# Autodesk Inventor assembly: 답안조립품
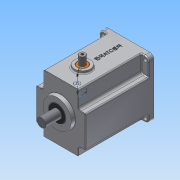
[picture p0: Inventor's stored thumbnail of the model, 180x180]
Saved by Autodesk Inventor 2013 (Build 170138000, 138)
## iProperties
Created: 2016-02
Part Number: 답안조립품
Document SubType Name: Assembly
Designer: Administrator
Author: Administrator
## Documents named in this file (13)
- C:\Users\Administrator\Desktop\360212V1023\답안조립품.iam
- C:\Users\Administrator\Desktop\360212V1023\본체.ipt
- C:\Users\Administrator\Desktop\360212V1023\커버.ipt
- C:\Users\Administrator\Desktop\360212V1023\오일실 17 32 8.ipt
- C:\Users\Administrator\Desktop\360212V1023\오일실 8 22 7.ipt
- C:\Users\Administrator\Desktop\360212V1023\부시.ipt
- C:\Users\Administrator\Desktop\360212V1023\베어링 608.ipt
- C:\Users\Administrator\Desktop\360212V1023\베어링 6003.ipt
- C:\Users\Administrator\Desktop\360212V1023\볼트 M4 x 10.ipt
- C:\Users\Administrator\Desktop\360212V1023\슬라이더.ipt
- C:\Users\Administrator\Desktop\360212V1023\메인축.ipt
- C:\Users\Administrator\Desktop\360212V1023\서브축.ipt
- C:\Users\Administrator\Desktop\360212V1023\가변스프링1.ipt
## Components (3 placed, 2 different names)
1. ISO 4762 M4 x 10:1
2. ISO 4762 M4 x 10:2
3. 가변스프링1:1
